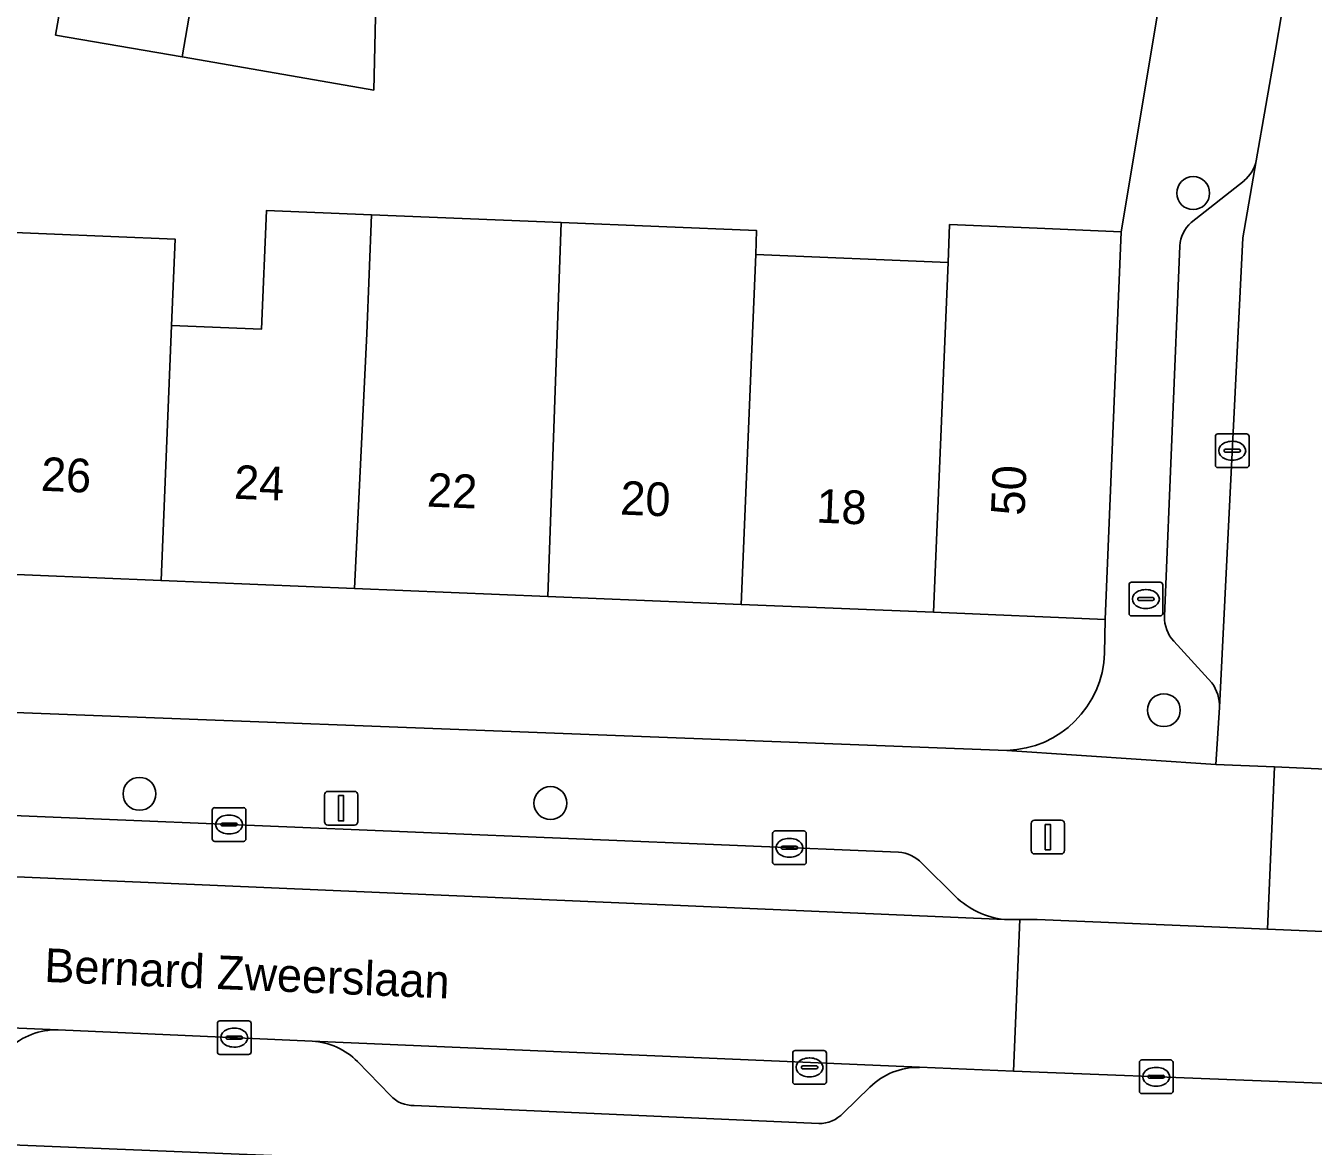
# Model space of a CAD drawing. Extents: x 159817 to 160765, y 380688 to 381638.
# Drawn here: x 160074.27 to 160112.52, y 380865.42 to 380898.7 of the extents above; entities that cross this region are included whole.
import ezdxf

# ---------------------------------------------------------------- set-up
doc = ezdxf.new("R2010")
doc.units = 0
for name, color, linetype in [('IMGEO_Berm_groen', 7, 'Continuous'), ('IMGEO_Boom', 7, 'Continuous'), ('IMGEO_Brandkraan', 7, 'Continuous'), ('IMGEO_Erf', 7, 'Continuous'), ('IMGEO_Kolk', 7, 'Continuous'), ('IMGEO_Lichtmast', 7, 'Continuous'), ('IMGEO_Openbare_ruimte_label', 7, 'Continuous'), ('IMGEO_Pand', 7, 'Continuous'), ('IMGEO_Pand_nummerreeks', 7, 'Continuous'), ('IMGEO_Parkeervlak_open', 7, 'Continuous'), ('IMGEO_Rijbaan_lokaal_open', 7, 'Continuous'), ('IMGEO_Rioolput', 7, 'Continuous'), ('IMGEO_Voetpad_open', 7, 'Continuous')]:
    doc.layers.add(name, color=color, linetype=linetype)

msp = doc.modelspace()

# ---------------------------------------------------------------- linework, layer by layer
at = {"layer": 'IMGEO_Berm_groen'}
msp.add_lwpolyline([(160170.952, 380848.196), (160169.444, 380861.549), (160005.773, 380868.257), (159996.586, 380868.629), (159996.603, 380869.516), (159993.946, 380869.644), (159993.895, 380868.739), (159985.923, 380869.026)], dxfattribs=at)
at = {"layer": 'IMGEO_Boom'}
for centre in [(160108.949, 380893.73), (160108.078, 380878.374), (160077.648, 380875.89), (160089.856, 380875.615)]:
    msp.add_circle(centre, 0.489, dxfattribs=at)
at = {"layer": 'IMGEO_Brandkraan'}
for p, q in [((160107.043, 380881.248), (160107.043, 380882.1)), ((160107.118, 380882.174), (160107.97, 380882.174)), ((160108.044, 380882.1), (160108.044, 380881.248)), ((160107.302, 380881.668), (160107.302, 380881.68)), ((160107.74, 380881.631), (160107.342, 380881.631)), ((160107.345, 380881.717), (160107.743, 380881.717)), ((160107.531, 380881.954), (160107.556, 380881.954)), ((160107.786, 380881.68), (160107.786, 380881.668)), ((160107.554, 380881.394), (160107.529, 380881.394)), ((160107.97, 380881.174), (160107.118, 380881.174))]:
    msp.add_line(p, q, dxfattribs=at)
for points in [[(160107.043, 380881.248), (160107.043, 380882.1)], [(160107.118, 380882.174), (160107.97, 380882.174)], [(160108.044, 380882.1), (160108.044, 380881.248)], [(160107.97, 380881.174), (160107.118, 380881.174)]]:
    msp.add_lwpolyline(points, dxfattribs=at)
for centre, radius, start, end in [((160107.12, 380882.098), 0.0765, 91.552, 178.448), ((160107.12, 380882.098), 0.0765, 91.552, 178.448), ((160107.968, 380882.098), 0.0765, 1.552, 88.448), ((160107.968, 380882.098), 0.0765, 1.552, 88.448), ((160107.342, 380881.677), 0.0403, 85.8775, 175.7526), ((160107.339, 380881.667), 0.0366, 178.938, 274.7102), ((160107.743, 380881.674), 0.043, 264.8664, 352.4533), ((160107.747, 380881.679), 0.0386, 1.7309, 96.639), ((160107.12, 380881.25), 0.0765, 181.552, 268.448), ((160107.12, 380881.25), 0.0765, 181.552, 268.448), ((160107.968, 380881.25), 0.0765, 271.552, 358.448), ((160107.968, 380881.25), 0.0765, 271.552, 358.448)]:
    msp.add_arc(centre, radius, start, end, dxfattribs=at)
for centre, major_axis, ratio, start_param, end_param in [((160107.53, 380881.674), (-0.387, 0.002), 0.722429, 4.712389, 7.853982), ((160107.555, 380881.674), (-0.39, 0.002), 0.717154, 1.570796, 4.712389)]:
    msp.add_ellipse(centre, major_axis=major_axis, ratio=ratio, start_param=start_param, end_param=end_param, dxfattribs=at)
at = {"layer": 'IMGEO_Erf'}
for points in [[(160084.665, 380899.389), (160084.608, 380896.788), (160083.985, 380896.896), (160078.919, 380897.773), (160075.155, 380898.425), (160075.594, 380900.961)], [(160057.321, 380899.721), (160056.447, 380894.607), (160058.947, 380894.505), (160061.561, 380894.398), (160061.506, 380893.07), (160067.218, 380892.835), (160072.962, 380892.599), (160078.707, 380892.362), (160078.602, 380889.801), (160081.274, 380889.691), (160081.418, 380893.212), (160084.542, 380893.084), (160090.175, 380892.853), (160095.982, 380892.615), (160095.953, 380891.905), (160101.668, 380891.67), (160101.714, 380892.793), (160104.319, 380892.686), (160106.808, 380892.584), (160108.066, 380900.123)], [(160101.239, 380881.28), (160095.526, 380881.515), (160089.781, 380881.751), (160084.036, 380881.987), (160078.29, 380882.223), (160072.545, 380882.459), (160066.8, 380882.695), (160061.09, 380882.929), (160055.976, 380883.139), (160055.871, 380882.322)], [(160106.316, 380880.068), (160106.335, 380881.071), (160101.239, 380881.28)], [(160058.577, 380878.925), (160062.579, 380878.745), (160103.417, 380877.179)]]:
    msp.add_lwpolyline(points, dxfattribs=at)
msp.add_arc((160103.33, 380880.165), 2.987, 271.6605, 358.1415, dxfattribs=at)
at = {"layer": 'IMGEO_Kolk'}
for p, q in [((160109.608, 380885.653), (160109.608, 380886.505)), ((160109.683, 380886.579), (160110.535, 380886.579)), ((160110.096, 380886.359), (160110.121, 380886.359)), ((160110.609, 380886.505), (160110.609, 380885.653)), ((160109.867, 380886.073), (160109.867, 380886.085)), ((160110.305, 380886.036), (160109.907, 380886.036)), ((160109.91, 380886.122), (160110.308, 380886.122)), ((160110.351, 380886.085), (160110.351, 380886.073)), ((160110.535, 380885.579), (160109.683, 380885.579)), ((160110.119, 380885.799), (160110.094, 380885.799)), ((160079.809, 380874.553), (160079.809, 380875.405)), ((160079.884, 380875.479), (160080.736, 380875.479)), ((160080.297, 380875.259), (160080.322, 380875.259)), ((160080.81, 380875.405), (160080.81, 380874.553)), ((160080.068, 380874.973), (160080.068, 380874.985)), ((160080.506, 380874.936), (160080.108, 380874.936)), ((160080.111, 380875.022), (160080.509, 380875.022)), ((160080.552, 380874.985), (160080.552, 380874.973)), ((160096.53, 380874.788), (160097.382, 380874.788)), ((160080.736, 380874.479), (160079.884, 380874.479)), ((160080.32, 380874.699), (160080.295, 380874.699)), ((160096.455, 380873.862), (160096.455, 380874.714)), ((160096.943, 380874.568), (160096.968, 380874.568)), ((160097.456, 380874.714), (160097.456, 380873.862)), ((160096.714, 380874.282), (160096.714, 380874.294)), ((160097.152, 380874.245), (160096.754, 380874.245)), ((160096.757, 380874.331), (160097.155, 380874.331)), ((160096.966, 380874.008), (160096.941, 380874.008)), ((160097.198, 380874.294), (160097.198, 380874.282)), ((160097.382, 380873.788), (160096.53, 380873.788)), ((160079.962, 380868.223), (160079.962, 380869.075)), ((160080.037, 380869.149), (160080.889, 380869.149)), ((160080.963, 380869.075), (160080.963, 380868.223)), ((160080.221, 380868.643), (160080.221, 380868.655)), ((160080.264, 380868.692), (160080.662, 380868.692)), ((160080.45, 380868.929), (160080.475, 380868.929)), ((160080.705, 380868.655), (160080.705, 380868.643)), ((160080.659, 380868.606), (160080.261, 380868.606)), ((160080.473, 380868.369), (160080.448, 380868.369)), ((160097.127, 380868.266), (160097.979, 380868.266)), ((160080.889, 380868.149), (160080.037, 380868.149)), ((160097.052, 380867.34), (160097.052, 380868.192)), ((160097.54, 380868.046), (160097.565, 380868.046)), ((160098.053, 380868.192), (160098.053, 380867.34)), ((160097.311, 380867.76), (160097.311, 380867.772)), ((160097.749, 380867.723), (160097.351, 380867.723)), ((160097.354, 380867.809), (160097.752, 380867.809)), ((160097.563, 380867.486), (160097.538, 380867.486)), ((160097.795, 380867.772), (160097.795, 380867.76)), ((160097.979, 380867.266), (160097.127, 380867.266))]:
    msp.add_line(p, q, dxfattribs=at)
for points in [[(160109.608, 380885.653), (160109.608, 380886.505)], [(160109.683, 380886.579), (160110.535, 380886.579)], [(160110.609, 380886.505), (160110.609, 380885.653)], [(160110.535, 380885.579), (160109.683, 380885.579)], [(160079.809, 380874.553), (160079.809, 380875.405)], [(160079.884, 380875.479), (160080.736, 380875.479)], [(160080.81, 380875.405), (160080.81, 380874.553)], [(160096.53, 380874.788), (160097.382, 380874.788)], [(160080.736, 380874.479), (160079.884, 380874.479)], [(160096.455, 380873.862), (160096.455, 380874.714)], [(160097.456, 380874.714), (160097.456, 380873.862)], [(160097.382, 380873.788), (160096.53, 380873.788)], [(160079.962, 380868.223), (160079.962, 380869.075)], [(160080.037, 380869.149), (160080.889, 380869.149)], [(160080.963, 380869.075), (160080.963, 380868.223)], [(160097.127, 380868.266), (160097.979, 380868.266)], [(160080.889, 380868.149), (160080.037, 380868.149)], [(160097.052, 380867.34), (160097.052, 380868.192)], [(160098.053, 380868.192), (160098.053, 380867.34)], [(160097.979, 380867.266), (160097.127, 380867.266)]]:
    msp.add_lwpolyline(points, dxfattribs=at)
for centre, radius, start, end in [((160109.685, 380886.503), 0.0765, 91.552, 178.448), ((160109.685, 380886.503), 0.0765, 91.552, 178.448), ((160110.533, 380886.503), 0.0765, 1.552, 88.448), ((160110.533, 380886.503), 0.0765, 1.552, 88.448), ((160109.907, 380886.082), 0.0403, 85.8775, 175.7526), ((160109.904, 380886.072), 0.0366, 178.938, 274.7102), ((160110.308, 380886.079), 0.043, 264.8664, 352.4533), ((160110.312, 380886.084), 0.0386, 1.7309, 96.639), ((160109.685, 380885.655), 0.0765, 181.552, 268.448), ((160109.685, 380885.655), 0.0765, 181.552, 268.448), ((160110.533, 380885.655), 0.0765, 271.552, 358.448), ((160110.533, 380885.655), 0.0765, 271.552, 358.448), ((160079.886, 380875.403), 0.0765, 91.552, 178.448), ((160079.886, 380875.403), 0.0765, 91.552, 178.448), ((160080.734, 380875.403), 0.0765, 1.552, 88.448), ((160080.734, 380875.403), 0.0765, 1.552, 88.448), ((160080.108, 380874.982), 0.0403, 85.8775, 175.7526), ((160080.105, 380874.972), 0.0366, 178.938, 274.7102), ((160080.509, 380874.979), 0.043, 264.8664, 352.4533), ((160080.513, 380874.984), 0.0386, 1.7309, 96.639), ((160096.532, 380874.712), 0.0765, 91.552, 178.448), ((160096.532, 380874.712), 0.0765, 91.552, 178.448), ((160097.38, 380874.712), 0.0765, 1.552, 88.448), ((160097.38, 380874.712), 0.0765, 1.552, 88.448), ((160079.886, 380874.555), 0.0765, 181.552, 268.448), ((160079.886, 380874.555), 0.0765, 181.552, 268.448), ((160080.734, 380874.555), 0.0765, 271.552, 358.448), ((160080.734, 380874.555), 0.0765, 271.552, 358.448), ((160096.754, 380874.291), 0.0403, 85.8775, 175.7526), ((160096.751, 380874.281), 0.0366, 178.938, 274.7102), ((160097.155, 380874.288), 0.043, 264.8664, 352.4533), ((160097.159, 380874.293), 0.0386, 1.7309, 96.639), ((160096.532, 380873.864), 0.0765, 181.552, 268.448), ((160096.532, 380873.864), 0.0765, 181.552, 268.448), ((160097.38, 380873.864), 0.0765, 271.552, 358.448), ((160097.38, 380873.864), 0.0765, 271.552, 358.448), ((160080.039, 380869.073), 0.0765, 91.552, 178.448), ((160080.039, 380869.073), 0.0765, 91.552, 178.448), ((160080.887, 380869.073), 0.0765, 1.552, 88.448), ((160080.887, 380869.073), 0.0765, 1.552, 88.448), ((160080.261, 380868.652), 0.0403, 85.8775, 175.7526), ((160080.258, 380868.642), 0.0366, 178.938, 274.7102), ((160080.662, 380868.649), 0.043, 264.8664, 352.4533), ((160080.666, 380868.654), 0.0386, 1.7309, 96.639), ((160097.129, 380868.19), 0.0765, 91.552, 178.448), ((160097.129, 380868.19), 0.0765, 91.552, 178.448), ((160097.977, 380868.19), 0.0765, 1.552, 88.448), ((160097.977, 380868.19), 0.0765, 1.552, 88.448), ((160080.039, 380868.225), 0.0765, 181.552, 268.448), ((160080.039, 380868.225), 0.0765, 181.552, 268.448), ((160080.887, 380868.225), 0.0765, 271.552, 358.448), ((160080.887, 380868.225), 0.0765, 271.552, 358.448), ((160097.351, 380867.769), 0.0403, 85.8775, 175.7526), ((160097.348, 380867.759), 0.0366, 178.938, 274.7102), ((160097.752, 380867.766), 0.043, 264.8664, 352.4533), ((160097.756, 380867.771), 0.0386, 1.7309, 96.639), ((160097.129, 380867.342), 0.0765, 181.552, 268.448), ((160097.129, 380867.342), 0.0765, 181.552, 268.448), ((160097.977, 380867.342), 0.0765, 271.552, 358.448), ((160097.977, 380867.342), 0.0765, 271.552, 358.448)]:
    msp.add_arc(centre, radius, start, end, dxfattribs=at)
for centre, major_axis, ratio, start_param, end_param in [((160110.095, 380886.079), (-0.387, 0.002), 0.722429, 4.712389, 7.853982), ((160110.12, 380886.079), (-0.39, 0.002), 0.717154, 1.570796, 4.712389), ((160080.296, 380874.979), (-0.387, 0.002), 0.722429, 4.712389, 7.853982), ((160080.321, 380874.979), (-0.39, 0.002), 0.717154, 1.570796, 4.712389), ((160096.942, 380874.288), (-0.387, 0.002), 0.722429, 4.712389, 7.853982), ((160096.967, 380874.288), (-0.39, 0.002), 0.717154, 1.570796, 4.712389), ((160080.449, 380868.649), (-0.387, 0.002), 0.722429, 4.712389, 7.853982), ((160080.474, 380868.649), (-0.39, 0.002), 0.717154, 1.570796, 4.712389), ((160097.539, 380867.766), (-0.387, 0.002), 0.722429, 4.712389, 7.853982), ((160097.564, 380867.766), (-0.39, 0.002), 0.717154, 1.570796, 4.712389)]:
    msp.add_ellipse(centre, major_axis=major_axis, ratio=ratio, start_param=start_param, end_param=end_param, dxfattribs=at)
at = {"layer": 'IMGEO_Lichtmast'}
for p, q in [((160083.242, 380875.963), (160084.032, 380875.963)), ((160084.032, 380875.963), (160083.242, 380875.963)), ((160083.142, 380875.063), (160083.142, 380875.863)), ((160083.142, 380875.863), (160083.142, 380875.063)), ((160084.132, 380875.863), (160084.132, 380875.063)), ((160084.132, 380875.063), (160084.132, 380875.863)), ((160084.032, 380874.963), (160083.242, 380874.963)), ((160083.242, 380874.963), (160084.032, 380874.963)), ((160104.137, 380874.205), (160104.137, 380875.005)), ((160104.137, 380875.005), (160104.137, 380874.205)), ((160104.237, 380875.105), (160105.027, 380875.105)), ((160105.027, 380875.105), (160104.237, 380875.105)), ((160105.127, 380875.005), (160105.127, 380874.205)), ((160105.127, 380874.205), (160105.127, 380875.005)), ((160105.027, 380874.105), (160104.237, 380874.105)), ((160104.237, 380874.105), (160105.027, 380874.105))]:
    msp.add_line(p, q, dxfattribs=at)
for points in [[(160083.562, 380875.838), (160083.712, 380875.838), (160083.712, 380875.088), (160083.562, 380875.088), (160083.562, 380875.838)], [(160104.557, 380874.98), (160104.707, 380874.98), (160104.707, 380874.23), (160104.557, 380874.23), (160104.557, 380874.98)]]:
    msp.add_lwpolyline(points, dxfattribs=at)
for centre, start, end in [((160083.242, 380875.863), 90, 180), ((160083.242, 380875.863), 90, 180), ((160084.032, 380875.863), 0, 90), ((160084.032, 380875.863), 360, 90), ((160083.242, 380875.063), 180, 270), ((160083.242, 380875.063), 180, 270), ((160084.032, 380875.063), 270, 0), ((160084.032, 380875.063), 270, 0), ((160104.237, 380875.005), 90, 180), ((160104.237, 380875.005), 90, 180), ((160105.027, 380875.005), 0, 90), ((160105.027, 380875.005), 360, 90), ((160104.237, 380874.205), 180, 270), ((160104.237, 380874.205), 180, 270), ((160105.027, 380874.205), 270, 0), ((160105.027, 380874.205), 270, 0)]:
    msp.add_arc(centre, 0.1, start, end, dxfattribs=at)
at = {"layer": 'IMGEO_Pand'}
for points in [[(160079.355, 380900.309), (160075.594, 380900.961), (160075.155, 380898.425), (160078.919, 380897.773)], [(160084.424, 380899.431), (160079.355, 380900.309), (160078.919, 380897.773), (160083.985, 380896.896), (160084.608, 380896.788), (160084.665, 380899.389)], [(160084.398, 380889.563), (160084.542, 380893.084), (160081.418, 380893.212), (160081.274, 380889.691), (160078.602, 380889.801), (160078.29, 380882.223), (160084.036, 380881.987)], [(160089.781, 380881.751), (160090.175, 380892.853), (160084.542, 380893.084), (160084.398, 380889.563), (160084.036, 380881.987)], [(160095.837, 380889.093), (160095.953, 380891.905), (160095.982, 380892.615), (160090.175, 380892.853), (160089.781, 380881.751), (160095.526, 380881.515)], [(160106.808, 380892.584), (160104.319, 380892.686), (160101.714, 380892.793), (160101.668, 380891.67), (160101.552, 380888.858), (160101.239, 380881.28), (160106.335, 380881.071)], [(160078.602, 380889.801), (160078.707, 380892.362), (160072.962, 380892.599), (160072.856, 380890.026), (160072.545, 380882.459), (160078.29, 380882.223)], [(160101.552, 380888.858), (160101.668, 380891.67), (160095.953, 380891.905), (160095.837, 380889.093), (160095.526, 380881.515), (160101.239, 380881.28)]]:
    msp.add_lwpolyline(points, close=True, dxfattribs=at)
at = {"layer": 'IMGEO_Parkeervlak_open'}
for points in [[(160109.736, 380878.45), (160110.421, 380892.404), (160110.823, 380894.689)], [(160110.459, 380894.099), (160108.889, 380892.852)], [(160108.554, 380892.164), (160108.099, 380881.155)], [(160108.373, 380880.423), (160109.508, 380879.19)], [(160100.196, 380874.153), (160057.142, 380875.938)], [(160054.135, 380874.282), (160054.971, 380874.246), (160103.343, 380872.158)], [(160101.886, 380872.837), (160100.888, 380873.827)], [(160075.23, 380868.883), (160057.268, 380869.647)], [(160100.815, 380867.768), (160082.781, 380868.547)], [(160084.127, 380867.939), (160085.107, 380866.927)], [(160098.551, 380866.407), (160099.346, 380867.182)], [(160085.806, 380866.638), (160097.829, 380866.095)]]:
    msp.add_lwpolyline(points, dxfattribs=at)
for centre, radius, start, end in [((160109.81, 380894.907), 1.036, 308.7889, 347.8661), ((160109.503, 380892.128), 0.949, 130.273, 177.8023), ((160109.118, 380881.119), 1.02, 177.9942, 223.0492), ((160108.405, 380878.445), 1.331, 0.2098, 34.0392), ((160100.151, 380873.159), 0.995, 42.1581, 87.3918), ((160103.612, 380874.637), 2.493, 226.2088, 263.8177), ((160075.192, 380866.778), 2.105, 88.9652, 132.6688), ((160082.649, 380866.46), 2.091, 45.0109, 86.3708), ((160100.779, 380865.724), 2.044, 88.9906, 134.5046), ((160085.766, 380867.53), 0.893, 222.4814, 272.5935), ((160097.836, 380867.07), 0.975, 269.576, 317.1656)]:
    msp.add_arc(centre, radius, start, end, dxfattribs=at)
at = {"layer": 'IMGEO_Rijbaan_lokaal_open'}
for points in [[(160113.106, 380876.611), (160113.376, 380884.116), (160113.751, 380891.769), (160123.634, 380949.453), (160120.309, 380950.025), (160112.512, 380904.594), (160112.145, 380902.423), (160111.391, 380897.971), (160110.823, 380894.689), (160110.421, 380892.404), (160109.736, 380878.45), (160109.622, 380876.765), (160111.364, 380876.688)], [(160054.971, 380874.246), (160054.79, 380869.752), (160057.268, 380869.647), (160075.23, 380868.883), (160082.781, 380868.547), (160100.815, 380867.768), (160103.608, 380867.658), (160103.797, 380872.159), (160103.343, 380872.158)], [(160117.285, 380871.609), (160111.159, 380871.87), (160104.313, 380872.161), (160103.797, 380872.159), (160103.608, 380867.658), (160117.81, 380867.096), (160117.994, 380871.561)]]:
    msp.add_lwpolyline(points, close=True, dxfattribs=at)
at = {"layer": 'IMGEO_Rioolput'}
for p, q in [((160107.35, 380867.061), (160107.35, 380867.913)), ((160107.425, 380867.987), (160108.277, 380867.987)), ((160108.351, 380867.913), (160108.351, 380867.061)), ((160107.609, 380867.481), (160107.609, 380867.493)), ((160107.652, 380867.53), (160108.05, 380867.53)), ((160107.838, 380867.767), (160107.863, 380867.767)), ((160108.093, 380867.493), (160108.093, 380867.481)), ((160108.047, 380867.444), (160107.649, 380867.444)), ((160107.861, 380867.207), (160107.836, 380867.207)), ((160108.277, 380866.987), (160107.425, 380866.987))]:
    msp.add_line(p, q, dxfattribs=at)
for points in [[(160107.35, 380867.061), (160107.35, 380867.913)], [(160107.425, 380867.987), (160108.277, 380867.987)], [(160108.351, 380867.913), (160108.351, 380867.061)], [(160108.277, 380866.987), (160107.425, 380866.987)]]:
    msp.add_lwpolyline(points, dxfattribs=at)
for centre, radius, start, end in [((160107.427, 380867.911), 0.0765, 91.552, 178.448), ((160107.427, 380867.911), 0.0765, 91.552, 178.448), ((160108.275, 380867.911), 0.0765, 1.552, 88.448), ((160108.275, 380867.911), 0.0765, 1.552, 88.448), ((160107.649, 380867.49), 0.0403, 85.8775, 175.7526), ((160107.646, 380867.48), 0.0366, 178.938, 274.7102), ((160108.05, 380867.487), 0.043, 264.8664, 352.4533), ((160108.054, 380867.492), 0.0386, 1.7309, 96.639), ((160107.427, 380867.063), 0.0765, 181.552, 268.448), ((160107.427, 380867.063), 0.0765, 181.552, 268.448), ((160108.275, 380867.063), 0.0765, 271.552, 358.448), ((160108.275, 380867.063), 0.0765, 271.552, 358.448)]:
    msp.add_arc(centre, radius, start, end, dxfattribs=at)
for centre, major_axis, ratio, start_param, end_param in [((160107.837, 380867.487), (-0.387, 0.002), 0.722429, 4.712389, 7.853982), ((160107.862, 380867.487), (-0.39, 0.002), 0.717154, 1.570796, 4.712389)]:
    msp.add_ellipse(centre, major_axis=major_axis, ratio=ratio, start_param=start_param, end_param=end_param, dxfattribs=at)
at = {"layer": 'IMGEO_Voetpad_open'}
for points in [[(160118.604, 380948.851), (160120.092, 380949.943), (160120.402, 380950.566), (160120.62, 380951.859), (160118.846, 380952.164), (160119.614, 380956.712), (160121.388, 380956.406), (160121.639, 380957.894), (160119.865, 380958.199), (160120.614, 380962.627), (160122.386, 380962.321), (160122.575, 380963.442), (160119.128, 380964.039), (160117.654, 380955.521), (160117.224, 380953.039), (160114.243, 380935.814), (160113.802, 380933.264), (160108.896, 380904.908), (160108.656, 380903.524), (160108.066, 380900.123), (160106.808, 380892.584), (160106.335, 380881.071), (160106.316, 380880.068)], [(160110.823, 380894.689), (160111.391, 380897.971), (160112.145, 380902.423)], [(160108.889, 380892.852), (160110.459, 380894.099)], [(160108.099, 380881.155), (160108.554, 380892.164)], [(160109.508, 380879.19), (160108.373, 380880.423)], [(160111.364, 380876.688), (160109.622, 380876.765), (160103.417, 380877.179), (160062.579, 380878.745), (160058.577, 380878.925)], [(160103.417, 380877.179), (160109.622, 380876.765), (160109.736, 380878.45)], [(160103.343, 380872.158), (160103.797, 380872.159), (160104.313, 380872.161), (160111.159, 380871.87), (160111.364, 380876.688)], [(160169.052, 380874.016), (160163.251, 380874.767), (160118.85, 380876.572), (160113.106, 380876.611), (160111.364, 380876.688), (160111.159, 380871.87), (160117.285, 380871.609), (160117.994, 380871.561), (160118.45, 380871.532)], [(160057.142, 380875.938), (160100.196, 380874.153)], [(160100.888, 380873.827), (160101.886, 380872.837)], [(159985.923, 380869.026), (159993.895, 380868.739), (159993.946, 380869.644), (159996.603, 380869.516), (159996.586, 380868.629), (160005.773, 380868.257), (160169.444, 380861.549), (160169.293, 380862.879), (160168.811, 380864.208)], [(160082.781, 380868.547), (160075.23, 380868.883)], [(160085.107, 380866.927), (160084.127, 380867.939)], [(160122.045, 380866.92), (160120.123, 380867.005), (160117.81, 380867.096), (160103.608, 380867.658), (160100.815, 380867.768)], [(160099.346, 380867.182), (160098.551, 380866.407)], [(160097.829, 380866.095), (160085.806, 380866.638)]]:
    msp.add_lwpolyline(points, dxfattribs=at)
for centre, radius, start, end in [((160109.81, 380894.907), 1.036, 308.7889, 347.8661), ((160109.503, 380892.128), 0.949, 130.273, 177.8023), ((160109.118, 380881.119), 1.02, 177.9942, 223.0492), ((160103.33, 380880.165), 2.987, 271.6605, 358.1415), ((160108.405, 380878.445), 1.331, 0.2098, 34.0392), ((160100.151, 380873.159), 0.995, 42.1581, 87.3918), ((160103.612, 380874.637), 2.493, 226.2088, 263.8177), ((160075.192, 380866.778), 2.105, 88.9652, 132.6688), ((160082.649, 380866.46), 2.091, 45.0109, 86.3708), ((160100.779, 380865.724), 2.044, 88.9906, 134.5046), ((160085.766, 380867.53), 0.893, 222.4814, 272.5935), ((160097.836, 380867.07), 0.975, 269.576, 317.1656)]:
    msp.add_arc(centre, radius, start, end, dxfattribs=at)

# ---------------------------------------------------------------- texts
at = {"layer": 'IMGEO_Openbare_ruimte_label'}
msp.add_text('Bernard Zweerslaan', height=1, rotation=357.6498, dxfattribs=at).set_placement((160074.809, 380870.306))
at = {"layer": 'IMGEO_Pand_nummerreeks'}
for s, rotation, p in [('26', 357.6509, (160074.707, 380884.892)), ('24', 357.6509, (160080.442, 380884.656)), ('50', 87.6454, (160103.939, 380884.141)), ('22', 357.6485, (160086.175, 380884.422)), ('20', 357.6509, (160091.916, 380884.185)), ('18', 357.6509, (160097.743, 380883.947))]:
    msp.add_text(s, height=1, rotation=rotation, dxfattribs=at).set_placement(p)

doc.saveas('drawing.dxf')
